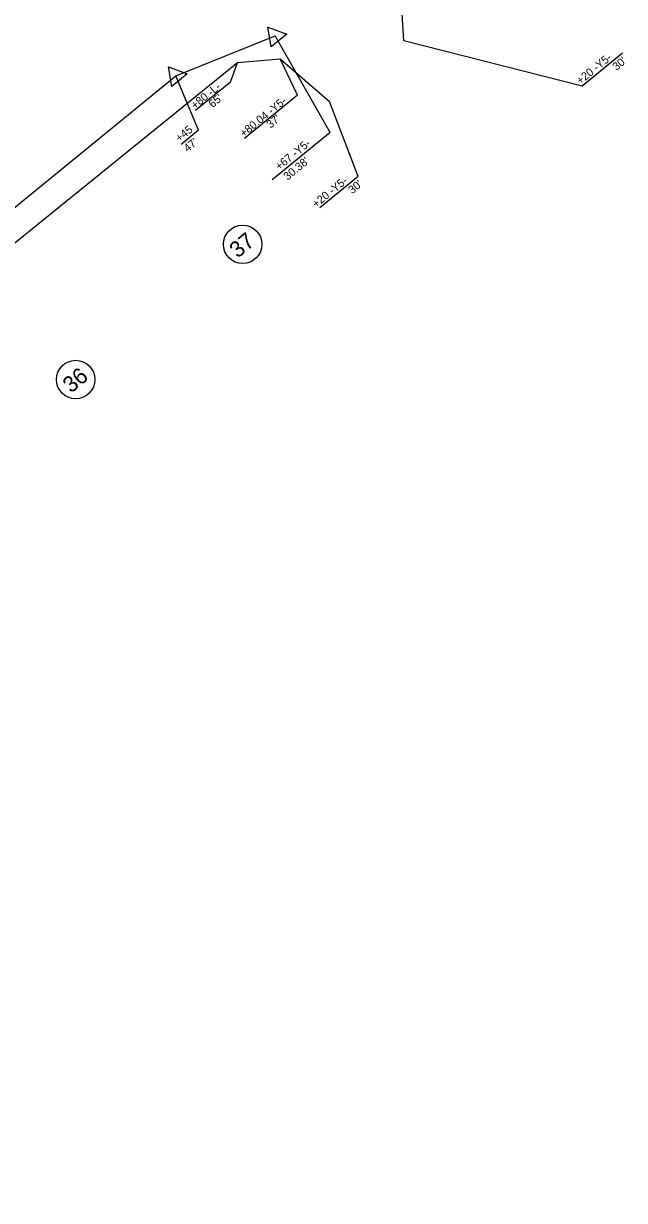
# Model space of a CAD drawing. Extents: x 2320946 to 2332748, y 597838 to 612698.
# Drawn here: x 2322959 to 2323334, y 598373 to 599108 of the extents above; entities that cross this region are included whole.
import ezdxf

# ---------------------------------------------------------------- set-up
doc = ezdxf.new("R2010")
doc.units = 0
for name, color, linetype in [('Prop Easement Construction', 7, 'Continuous'), ('Prop Easement Construction Station Offsets', 7, 'Continuous'), ('Prop Parcel Number CELL', 7, 'Continuous'), ('Prop ROW Marker CELL', 7, 'Continuous'), ('Prop ROW RW Lines', 7, 'Continuous'), ('Prop ROW Station Offsets', 7, 'Continuous')]:
    doc.layers.add(name, color=color, linetype=linetype)

msp = doc.modelspace()

# ---------------------------------------------------------------- linework, layer by layer
at = {"layer": 'Prop Easement Construction'}
for p, q in [((2323196.52, 599097.06), (2323193.8, 599139.98)), ((2322214.18, 598372.58), (2323092.68, 599083.33)), ((2323092.68, 599083.33), (2323119.34, 599085.72)), ((2323119.34, 599085.72), (2323150, 599059.16))]:
    msp.add_line(p, q, dxfattribs=at)
at = {"layer": 'Prop Easement Construction Station Offsets'}
for p, q in [((2323332.85, 599089.19), (2323307.73, 599068.69)), ((2323088.21, 599071.19), (2323066.5, 599053.46)), ((2323130.01, 599062.98), (2323096.95, 599035.99)), ((2323167.94, 599012.18), (2323144.01, 598992.64))]:
    msp.add_line(p, q, dxfattribs=at)
for points in [[(2323307.73, 599068.69), (2323196.52, 599097.06)], [(2323088.21, 599071.19), (2323092.68, 599083.33)], [(2323130.01, 599062.98), (2323119.34, 599085.72)], [(2323167.94, 599012.18), (2323150, 599059.16)]]:
    msp.add_lwpolyline(points, dxfattribs=at)
at = {"layer": 'Prop Parcel Number CELL'}
for p, q in [((2323095.9, 598969.86), (2323095.9, 598969.86)), ((2322991.67, 598885.39), (2322991.67, 598885.39))]:
    msp.add_line(p, q, dxfattribs=at)
for centre in [(2323095.9, 598969.86), (2322991.67, 598885.39)]:
    msp.add_circle(centre, 12, dxfattribs=at)
at = {"layer": 'Prop ROW Marker CELL'}
for p, q in [((2323116.23, 599100.01), (2323116.23, 599100.01)), ((2323054.19, 599075.13), (2323054.19, 599075.13))]:
    msp.add_line(p, q, dxfattribs=at)
for points in [[(2323113.67, 599093.27), (2323111.68, 599105.59), (2323123.35, 599101.18)], [(2323051.62, 599068.39), (2323049.63, 599080.71), (2323061.31, 599076.3)]]:
    msp.add_lwpolyline(points, close=True, dxfattribs=at)
at = {"layer": 'Prop ROW RW Lines'}
for p, q in [((2323054.19, 599075.13), (2323116.23, 599100.01)), ((2322511.94, 598632.45), (2323054.19, 599075.13))]:
    msp.add_line(p, q, dxfattribs=at)
at = {"layer": 'Prop ROW Station Offsets'}
for p, q in [((2323068.27, 599041.16), (2323057.42, 599032.31)), ((2323150.49, 599039.77), (2323114.32, 599010.24))]:
    msp.add_line(p, q, dxfattribs=at)
for points in [[(2323150.49, 599039.77), (2323150.47, 599039.75), (2323116.23, 599100.01)], [(2323068.27, 599041.16), (2323054.19, 599075.13)]]:
    msp.add_lwpolyline(points, dxfattribs=at)

# ---------------------------------------------------------------- texts
at = {"layer": 'Prop Easement Construction Station Offsets'}
for s, p in [('+20 -Y5-', (2323306.66, 599069.43)), ("30'", (2323329.14, 599078.1)), ('+80 -L-', (2323066.1, 599053.95)), ("65'", (2323077.08, 599054.84)), ('+80.04 -Y5-', (2323096.56, 599036.47)), ("37'", (2323113.21, 599042)), ('+20 -Y5-', (2323141.75, 598992.41)), ("30'", (2323164.23, 599001.09))]:
    msp.add_text(s, height=5, rotation=39.22799, dxfattribs=at).set_placement(p)
at = {"layer": 'Prop Parcel Number CELL'}
for s, p in [('37', (2323092.76, 598960.84)), ('36', (2322988.73, 598876.54))]:
    msp.add_text(s, height=10, rotation=39.22799, dxfattribs=at).set_placement(p)
at = {"layer": 'Prop ROW Station Offsets'}
for s, p in [('+45', (2323056.43, 599033.52)), ("47'", (2323061.57, 599027.22)), ('+67 -Y5-', (2323118.72, 599015.84)), ("30.38'", (2323123.85, 599009.55))]:
    msp.add_text(s, height=5, rotation=39.22799, dxfattribs=at).set_placement(p)

doc.saveas('drawing.dxf')
